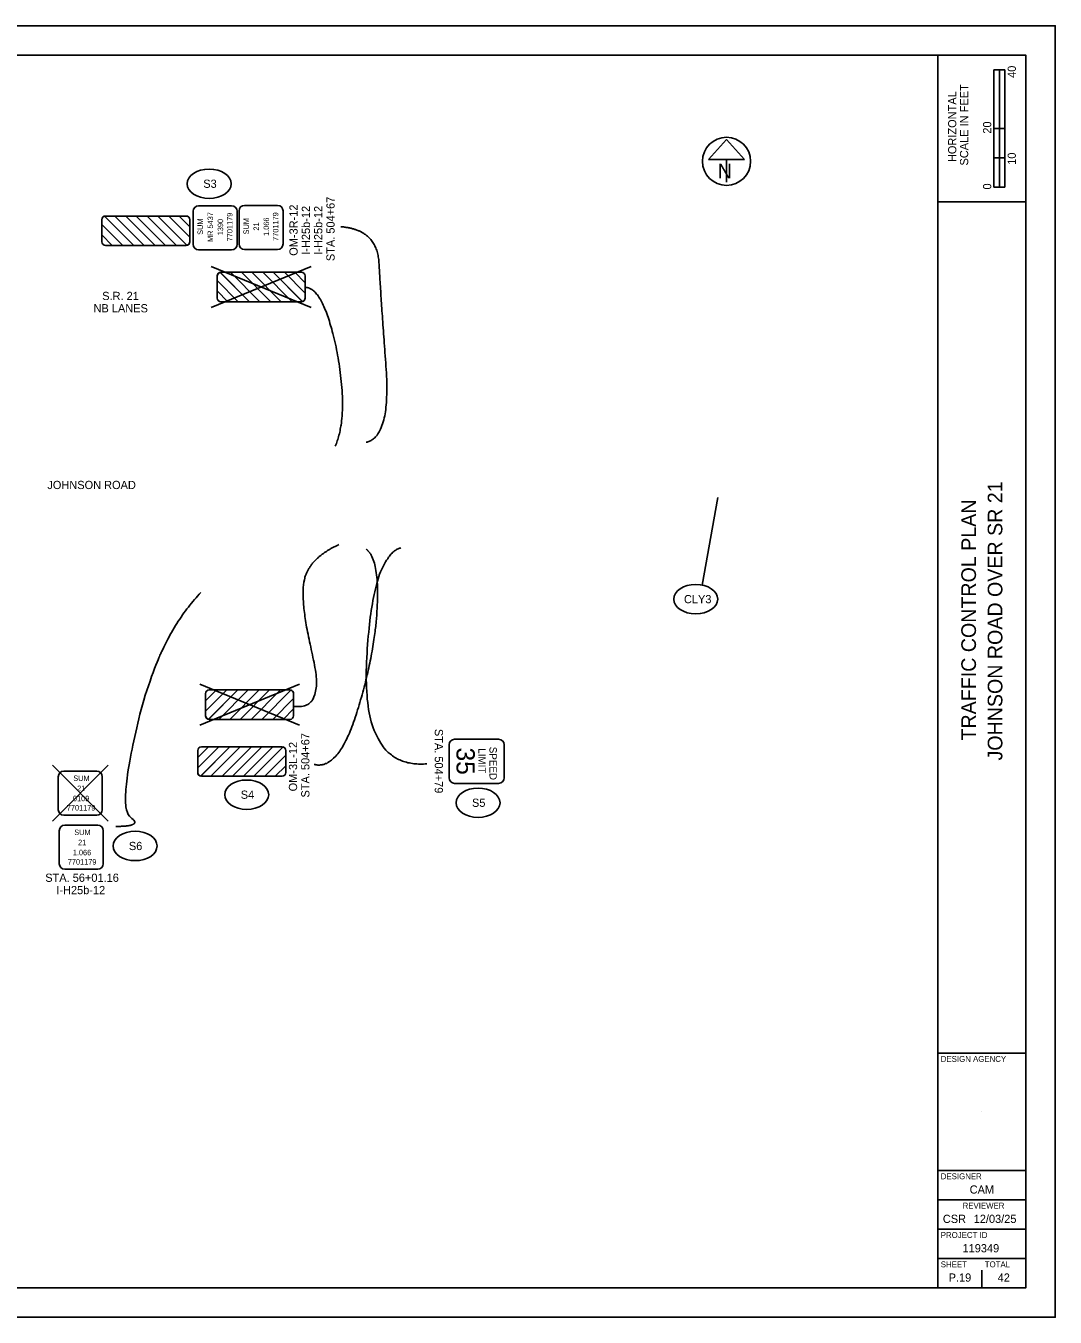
# Model space of a CAD drawing. Extents: x 0 to 680, y 0 to 440.
# Drawn here: x 329.1 to 680, y 0 to 440 of the extents above; entities that cross this region are included whole.
import ezdxf

# ---------------------------------------------------------------- set-up
doc = ezdxf.new("R2010")
doc.units = 0
for name, color, linetype in [('_CIVIL_CONSTRUCTION', 7, 'Continuous'), ('GE_X_Alignment', 7, 'Continuous'), ('GE_X_Alignment_100_Cardinal_Points', 7, 'Continuous'), ('GE_X_Alignment_100_Distances', 7, 'Continuous'), ('RW_X_CL', 7, 'Continuous'), ('RW_X_Esmt_SH', 7, 'Continuous'), ('RW_X_Fee_WL', 7, 'Continuous'), ('SV_X_Mon_Cells_Found', 7, 'Continuous')]:
    doc.layers.add(name, color=color, linetype=linetype)

msp = doc.modelspace()

# ---------------------------------------------------------------- linework, layer by layer
at = {"layer": '_CIVIL_CONSTRUCTION'}
for p, q in [((640, 10), (640, 430)), ((640, 380), (670, 380)), ((640, 90), (670, 90)), ((640, 50), (670, 50)), ((640, 40), (670, 40)), ((640, 30), (670, 30)), ((640, 20), (670, 20))]:
    msp.add_line(p, q, dxfattribs=at)
msp.add_lwpolyline([(30, 430), (670, 430), (670, 10), (30, 10)], close=True, dxfattribs=at)
at = {"layer": 'GE_X_Alignment'}
for p, q in [((659.13, 385), (659.13, 425)), ((662.88, 425), (659.13, 425)), ((659.13, 405), (659.13, 425)), ((659.13, 425), (661, 425)), ((661, 425), (661.02, 425)), ((661.02, 425), (661.02, 405)), ((662.88, 425), (662.88, 385)), ((661.02, 405), (659.13, 405)), ((662.87, 405), (661, 405)), ((661, 405), (661, 395)), ((662.87, 395), (662.87, 405)), ((661, 395), (659.13, 395)), ((659.13, 395), (659.13, 385)), ((661, 385), (661, 395)), ((661, 395), (662.87, 395)), ((662.88, 385), (659.13, 385)), ((659.13, 385), (661, 385)), ((655, 70), (655, 70)), ((647.5, 13.5), (647.5, 13.5)), ((655, 10), (655, 16))]:
    msp.add_line(p, q, dxfattribs=at)
at = {"layer": 'GE_X_Alignment_100_Cardinal_Points'}
for p, q in [((567.97, 401.3), (561.82, 394.48)), ((574.13, 394.48), (567.97, 401.3)), ((561.82, 394.48), (574.13, 394.48)), ((567.97, 394.48), (567.97, 386.74)), ((559.64, 249.44), (565.02, 279.24))]:
    msp.add_line(p, q, dxfattribs=at)
msp.add_circle((567.97, 393.83), 8.2, dxfattribs=at)
for centre in [(391.62, 386.2), (557.47, 244.65), (404.4, 178.03), (483.26, 175.28), (366.36, 160.55)]:
    msp.add_ellipse(centre, major_axis=(7.5, 0), ratio=0.666667, dxfattribs=at)
for points in [[(445.12, 298.1), (453.64, 299.96), (450.09, 348.13), (448.85, 370.54), (436.48, 371.55)], [(434.61, 296.75), (437.97, 304.84), (435.52, 330.74), (428.62, 350.96), (424.34, 350.86)], [(435.76, 263.22), (426.03, 258.74), (422.29, 244.76), (431.38, 206.4), (420.38, 208.17)], [(445.12, 261.7), (449.66, 258.32), (448.15, 225.93), (435.76, 186.21), (427.41, 188.33)], [(456.97, 262.16), (446.9, 259.15), (443.63, 186.82), (465.8, 188.52)], [(388.77, 246.88), (374.33, 232), (360.36, 173.41), (369.31, 167.21), (359.83, 167.21)]]:
    msp.add_open_spline(points, degree=2, dxfattribs=at)
at = {"layer": 'GE_X_Alignment_100_Distances'}
msp.add_circle((567.97, 393.83), 8.2, dxfattribs=at)
at = {"layer": 'RW_X_CL'}
msp.add_lwpolyline([(0, 0), (680, 0), (680, 440), (0, 440)], close=True, dxfattribs=at)
at = {"layer": 'RW_X_Fee_WL'}
for p, q in [((365.9, 365.2), (355.9, 375.2)), ((369.44, 365.2), (359.44, 375.2)), ((373.21, 365.2), (363.21, 375.2)), ((376.75, 365.2), (366.75, 375.2)), ((380.52, 365.2), (370.52, 375.2)), ((384.06, 365.2), (374.06, 375.2)), ((385.03, 368.01), (377.83, 375.2)), ((385.03, 371.54), (381.37, 375.2)), ((362.13, 365.2), (355.03, 372.31)), ((358.59, 365.2), (355.03, 368.77)), ((387.71, 187.14), (394.91, 194.34)), ((387.71, 190.68), (391.37, 194.34)), ((388.68, 184.34), (398.68, 194.34)), ((392.22, 184.34), (402.22, 194.34)), ((395.99, 184.34), (405.99, 194.34)), ((399.53, 184.34), (409.53, 194.34)), ((403.3, 184.34), (413.3, 194.34)), ((406.84, 184.34), (416.84, 194.34)), ((410.61, 184.34), (417.71, 191.44)), ((414.15, 184.34), (417.71, 187.91))]:
    msp.add_line(p, q, dxfattribs=at)
for points in [[(399.27, 378.68), (388.02, 378.68)], [(414.92, 378.81), (403.67, 378.81)], [(355.03, 373.95), (355.03, 372.31), (362.13, 365.2), (365.9, 365.2), (355.95, 375.16)], [(383.78, 375.2), (356.28, 375.2)], [(363.21, 375.2), (359.44, 375.2), (369.44, 365.2), (373.21, 365.2), (363.21, 375.2)], [(370.52, 375.2), (366.75, 375.2), (376.75, 365.2), (380.52, 365.2), (370.52, 375.2)], [(385.03, 366.45), (385.03, 368.01), (377.83, 375.2), (374.06, 375.2), (384.03, 365.23)], [(383.78, 375.2), (381.37, 375.2), (385.03, 371.54)], [(386.14, 376.8), (386.14, 365.55)], [(401.14, 365.55), (401.14, 376.8)], [(401.8, 376.94), (401.8, 365.69)], [(416.8, 365.69), (416.8, 376.94)], [(355.03, 373.95), (355.03, 366.45)], [(385.03, 366.45), (385.03, 373.95)], [(385.03, 371.54), (385.03, 373.95)], [(355.03, 368.77), (355.03, 366.45)], [(356.28, 365.2), (358.59, 365.2), (355.03, 368.77)], [(356.28, 365.2), (383.78, 365.2)], [(388.02, 363.68), (399.27, 363.68)], [(403.67, 363.81), (414.92, 363.81)], [(387.71, 185.59), (387.71, 187.14), (394.91, 194.34), (398.68, 194.34), (388.71, 184.36)], [(388.96, 194.34), (391.37, 194.34), (387.71, 190.68)], [(388.96, 194.34), (416.46, 194.34)], [(402.22, 194.34), (405.99, 194.34), (395.99, 184.34), (392.22, 184.34), (402.22, 194.34)], [(409.53, 194.34), (413.3, 194.34), (403.3, 184.34), (399.53, 184.34), (409.53, 194.34)], [(417.71, 193.09), (417.71, 191.44), (410.61, 184.34), (406.84, 184.34), (416.79, 194.29)], [(387.71, 185.59), (387.71, 193.09)], [(387.71, 190.68), (387.71, 193.09)], [(417.71, 193.09), (417.71, 185.59)], [(416.46, 184.34), (414.15, 184.34), (417.71, 187.91)], [(417.71, 187.91), (417.71, 185.59)], [(416.46, 184.34), (388.96, 184.34)], [(353.64, 167.62), (342.39, 167.62)], [(340.51, 165.74), (340.51, 154.49)], [(355.51, 154.49), (355.51, 165.74)], [(342.39, 152.62), (353.64, 152.62)]]:
    msp.add_lwpolyline(points, dxfattribs=at)
for centre, radius, start, end in [((388.02, 376.8), 1.88, 90, 180), ((399.27, 376.8), 1.88, 0, 90), ((403.67, 376.94), 1.88, 90, 180), ((414.92, 376.94), 1.88, 0, 90), ((356.28, 373.95), 1.25, 90, 180), ((356.28, 373.95), 1.25, 105.2763, 180), ((383.78, 373.95), 1.25, 0, 90), ((383.78, 373.95), 1.25, 0, 90), ((356.28, 366.45), 1.25, 180, 270), ((356.28, 366.45), 1.25, 180, 270), ((383.78, 366.45), 1.25, 270, 0), ((383.78, 366.45), 1.25, 281.732, 0), ((388.02, 365.55), 1.88, 180, 270), ((399.27, 365.55), 1.88, 270, 0), ((403.67, 365.69), 1.88, 180, 270), ((414.92, 365.69), 1.88, 270, 0), ((388.96, 193.09), 1.25, 90, 180), ((388.96, 193.09), 1.25, 90, 180), ((416.46, 193.09), 1.25, 0, 90), ((416.46, 193.09), 1.25, 0, 74.7237), ((388.96, 185.59), 1.25, 180, 270), ((388.96, 185.59), 1.25, 180, 258.268), ((416.46, 185.59), 1.25, 270, 0), ((416.46, 185.59), 1.25, 270, 0), ((342.39, 165.74), 1.88, 90, 180), ((353.64, 165.74), 1.88, 360, 90), ((342.39, 154.49), 1.88, 180, 270), ((353.64, 154.49), 1.88, 270, 360)]:
    msp.add_arc(centre, radius, start, end, dxfattribs=at)
at = {"layer": 'SV_X_Mon_Cells_Found'}
for p, q in [((392.34, 358.01), (426.34, 344.01)), ((426.34, 358.01), (392.34, 344.01)), ((394.34, 353.2), (401.54, 346.01)), ((395.31, 356.01), (405.31, 346.01)), ((398.85, 356.01), (408.85, 346.01)), ((402.62, 356.01), (412.62, 346.01)), ((406.16, 356.01), (416.16, 346.01)), ((409.93, 356.01), (419.93, 346.01)), ((413.46, 356.01), (423.46, 346.01)), ((417.24, 356.01), (424.34, 348.91)), ((420.77, 356.01), (424.34, 352.44)), ((394.34, 349.67), (398, 346.01)), ((388.38, 215.7), (422.38, 201.7)), ((422.38, 215.7), (388.38, 201.7)), ((390.38, 206.5), (397.58, 213.7)), ((390.38, 210.04), (394.05, 213.7)), ((391.35, 203.7), (401.35, 213.7)), ((394.89, 203.7), (404.89, 213.7)), ((398.66, 203.7), (408.66, 213.7)), ((402.2, 203.7), (412.2, 213.7)), ((405.97, 203.7), (415.97, 213.7)), ((409.51, 203.7), (419.51, 213.7)), ((413.28, 203.7), (420.38, 210.8)), ((416.82, 203.7), (420.38, 207.27)), ((338.18, 169.04), (357.18, 188.04)), ((338.18, 188.04), (357.18, 169.04))]:
    msp.add_line(p, q, dxfattribs=at)
for points in [[(394.34, 354.76), (394.34, 353.2), (401.54, 346.01), (405.31, 346.01), (395.34, 355.98)], [(394.34, 354.76), (394.34, 347.26)], [(423.09, 356.01), (395.59, 356.01)], [(408.85, 346.01), (412.62, 346.01), (402.62, 356.01), (398.85, 356.01), (408.85, 346.01)], [(416.16, 346.01), (419.93, 346.01), (409.93, 356.01), (406.16, 356.01), (416.16, 346.01)], [(424.34, 347.26), (424.34, 348.91), (417.24, 356.01), (413.46, 356.01), (423.42, 346.05)], [(423.09, 356.01), (420.77, 356.01), (424.34, 352.44)], [(424.34, 347.26), (424.34, 354.76)], [(424.34, 352.44), (424.34, 354.76)], [(394.34, 349.67), (394.34, 347.26)], [(395.59, 346.01), (398, 346.01), (394.34, 349.67)], [(395.59, 346.01), (423.09, 346.01)], [(390.38, 204.95), (390.38, 206.5), (397.58, 213.7), (401.35, 213.7), (391.38, 203.72)], [(391.63, 213.7), (394.05, 213.7), (390.38, 210.04)], [(390.38, 204.95), (390.38, 212.45)], [(390.38, 210.04), (390.38, 212.45)], [(391.63, 213.7), (419.13, 213.7)], [(404.89, 213.7), (408.66, 213.7), (398.66, 203.7), (394.89, 203.7), (404.89, 213.7)], [(412.2, 213.7), (415.97, 213.7), (405.97, 203.7), (402.2, 203.7), (412.2, 213.7)], [(420.38, 212.45), (420.38, 210.8), (413.28, 203.7), (409.51, 203.7), (419.46, 213.65)], [(420.38, 212.45), (420.38, 204.95)], [(419.13, 203.7), (416.82, 203.7), (420.38, 207.27)], [(420.38, 207.27), (420.38, 204.95)], [(419.13, 203.7), (391.63, 203.7)], [(473.41, 195.02), (473.41, 183.77)], [(490.29, 196.89), (475.29, 196.89)], [(492.16, 183.77), (492.16, 195.02)], [(353.3, 186.04), (342.05, 186.04)], [(340.18, 184.16), (340.18, 172.91)], [(355.18, 172.91), (355.18, 184.16)], [(475.29, 181.89), (490.29, 181.89)], [(342.05, 171.04), (353.3, 171.04)]]:
    msp.add_lwpolyline(points, dxfattribs=at)
for centre, radius, start, end in [((395.59, 354.76), 1.25, 90, 180), ((395.59, 354.76), 1.25, 101.732, 180), ((423.09, 354.76), 1.25, 0, 90), ((423.09, 354.76), 1.25, 360, 90), ((395.59, 347.26), 1.25, 180, 270), ((395.59, 347.26), 1.25, 180, 270), ((423.09, 347.26), 1.25, 270, 0), ((423.09, 347.26), 1.25, 285.2763, 360), ((391.63, 212.45), 1.25, 90, 180), ((391.63, 212.45), 1.25, 90, 180), ((419.13, 212.45), 1.25, 0, 90), ((419.13, 212.45), 1.25, 0, 74.7237), ((391.63, 204.95), 1.25, 180, 270), ((391.63, 204.95), 1.25, 180, 258.268), ((419.13, 204.95), 1.25, 270, 0), ((419.13, 204.95), 1.25, 270, 0), ((475.29, 195.02), 1.88, 90, 180), ((490.29, 195.02), 1.88, 0, 90), ((342.05, 184.16), 1.88, 90, 180), ((353.3, 184.16), 1.88, 0, 90), ((475.29, 183.77), 1.88, 180, 270), ((490.29, 183.77), 1.88, 270, 0), ((342.05, 172.91), 1.88, 180, 270), ((353.3, 172.91), 1.88, 270, 0)]:
    msp.add_arc(centre, radius, start, end, dxfattribs=at)

# ---------------------------------------------------------------- texts
at = {"layer": 'GE_X_Alignment'}
for s, height, p in [('40', 2.8, (666.61, 422.25)), ('SCALE IN FEET', 2.8, (650.35, 392.41)), ('HORIZONTAL', 2.8, (646.3, 393.58)), ('20', 2.8, (658.21, 403.25)), ('10', 2.8, (666.61, 392.65)), ('0', 2.8, (658.21, 384.23)), ('JOHNSON ROAD OVER SR 21', 5, (662, 189.67)), ('TRAFFIC CONTROL PLAN', 5, (653, 196.49))]:
    msp.add_text(s, height=height, rotation=90, dxfattribs=at).set_placement(p)
for s, height, p in [('DESIGN AGENCY', 2, (641, 87)), ('DESIGNER', 2, (641, 47)), ('CAM', 2.8, (650.85, 42.1)), ('REVIEWER', 2, (648.44, 37)), ('CSR', 2.8, (641.7, 32.1)), ('12/03/25', 2.8, (652.22, 32.1)), ('PROJECT ID', 2, (641, 27)), ('119349', 2.8, (648.41, 22.1)), ('SHEET', 2, (641, 17)), ('TOTAL', 2, (656, 17)), ('P.19', 2.8, (643.68, 12.1)), ('42', 2.8, (660.39, 12.1))]:
    msp.add_text(s, height=height, dxfattribs=at).set_placement(p)
at = {"layer": 'GE_X_Alignment_100_Cardinal_Points'}
for s, height, p in [('N', 5, (564.95, 388)), ('S3', 2.8, (389.59, 384.8)), ('S.R. 21 ', 2.8, (355.14, 346.57)), ('NB LANES', 2.8, (352.19, 342.37)), ('JOHNSON ROAD', 2.8, (336.45, 282.16)), ('CLY3', 2.8, (553.46, 243.25)), ('S4', 2.8, (402.37, 176.63)), ('S5', 2.8, (481.2, 173.88)), ('S6', 2.8, (364.24, 159.15))]:
    msp.add_text(s, height=height, dxfattribs=at).set_placement(p)
at = {"layer": 'RW_X_Esmt_SH'}
for s, rotation, p in [('OM-3R-12', 90, (421.77, 361.64)), ('I-H25b-12', 90, (425.97, 361.99)), ('I-H25b-12', 90, (430.17, 361.99)), ('STA. 504+67', 90, (434.37, 359.82)), ('STA. 504+67', 90, (425.78, 177.06)), ('STA. 504+79', 270, (468.5, 200.44)), ('OM-3L-12', 90, (421.58, 179.15))]:
    msp.add_text(s, height=2.8, rotation=rotation, dxfattribs=at).set_placement(p)
for s, p in [('STA. 56+01.16', (335.73, 148.33)), ('I-H25b-12', (339.51, 144.13))]:
    msp.add_text(s, height=2.8, dxfattribs=at).set_placement(p)
at = {"layer": 'RW_X_Fee_WL'}
for s, p in [('SUM', (389.5, 368.79)), ('MR 5437', (392.93, 366.34)), ('1390', (396.37, 368.63)), ('7701179', (399.54, 366.57)), ('SUM', (405.16, 368.92)), ('1.066', (412.03, 368.41)), ('7701179', (415.2, 366.71)), ('21', (408.59, 370.22))]:
    msp.add_text(s, height=1.875, rotation=90, dxfattribs=at).set_placement(p)
for s, p in [('SUM', (345.62, 164.26)), ('1.066', (345.12, 157.38)), ('21', (346.92, 160.82)), ('7701179', (343.41, 154.21))]:
    msp.add_text(s, height=1.875, dxfattribs=at).set_placement(p)
at = {"layer": 'SV_X_Mon_Cells_Found'}
for s, height, p in [('35', 6.25, (475.91, 194.09)), ('SPEED', 2.5, (487.16, 194.36)), ('LIMIT', 2.5, (483.41, 193.84))]:
    msp.add_text(s, height=height, rotation=270, dxfattribs=at).set_placement(p)
for s, p in [('SUM', (345.29, 182.68)), ('21', (346.59, 179.24)), ('0109', (345.16, 175.8)), ('7701179', (343.07, 172.63))]:
    msp.add_text(s, height=1.875, dxfattribs=at).set_placement(p)

doc.saveas('drawing.dxf')
